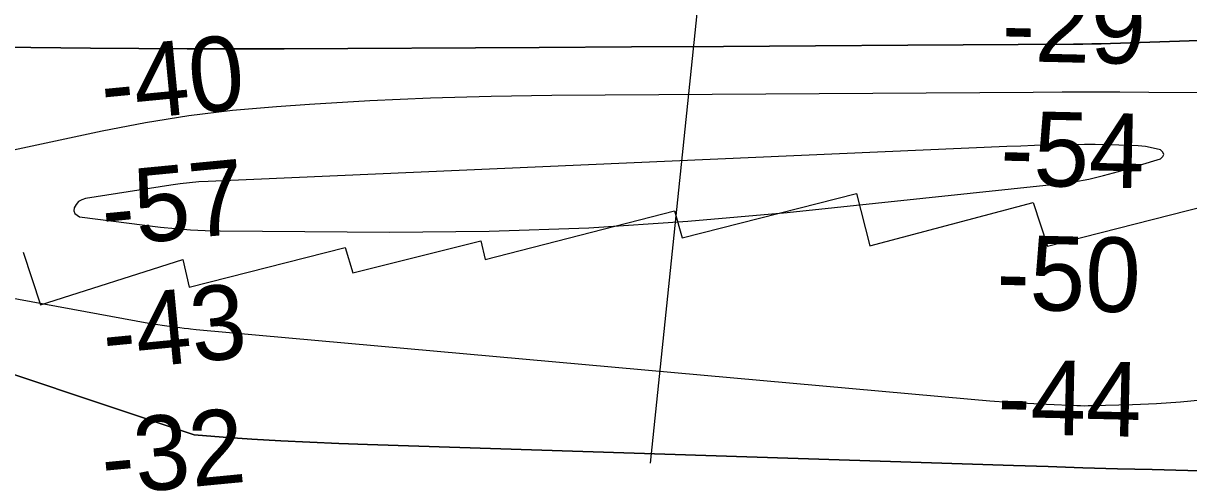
# Model space of a CAD drawing. Extents: x 3219052 to 3256913, y 800770 to 826146.
# Drawn here: x 3231171 to 3232109, y 817201 to 817568 of the extents above; entities that cross this region are included whole.
import ezdxf

# ---------------------------------------------------------------- set-up
doc = ezdxf.new("R2010")
doc.units = 0
for name, color, linetype in [('V-RIVR-RANG', 7, 'Continuous'), ('V-RRAP-RVMT', 7, 'Continuous'), ('V-TOPO-DPTH', 7, 'Continuous'), ('V-TOPO-MAJR', 7, 'Continuous'), ('V-TOPO-MINR', 7, 'Continuous')]:
    doc.layers.add(name, color=color, linetype=linetype)

msp = doc.modelspace()

# ---------------------------------------------------------------- linework, layer by layer
at = {"layer": 'V-RIVR-RANG'}
msp.add_line((3231742.15, 817854.6), (3231675.46, 817214.06), dxfattribs=at)
at = {"layer": 'V-RRAP-RVMT'}
msp.add_lwpolyline([(3231170.56, 817383.87), (3231184.32, 817341.3), (3231298.98, 817377.83), (3231304.2, 817355.77), (3231429.89, 817387.67), (3231435.99, 817367.07), (3231538.94, 817392.87), (3231542.59, 817377.99), (3231694.95, 817417.14), (3231701.22, 817395.43), (3231841.55, 817431.03), (3231852.44, 817388.93), (3231984.07, 817423.79), (3231995.51, 817388.51), (3232123.05, 817421.08)], dxfattribs=at)
at = {"layer": 'V-TOPO-DPTH'}
for points in [[(3232117.58, 817554.21), (3232046.13, 817551.79), (3232038.72, 817551.57), (3232031.31, 817551.39), (3232023.9, 817551.27), (3232016.5, 817551.19), (3231882.92, 817550.33), (3231808.73, 817549.87), (3231734.53, 817549.42), (3231660.33, 817549), (3231586.13, 817548.59), (3231380.67, 817547.49), (3231341.66, 817547.38), (3231302.65, 817547.4), (3231263.64, 817547.61), (3231224.63, 817547.96), (3230816.06, 817552.63), (3230771.39, 817553.09), (3230726.72, 817553.47), (3230682.05, 817553.73), (3230637.37, 817553.93)], [(3230637.37, 817553.93), (3230682.05, 817553.73), (3230726.72, 817553.47), (3230771.39, 817553.09), (3230816.06, 817552.63), (3231224.63, 817547.96), (3231263.64, 817547.61), (3231302.65, 817547.4), (3231341.66, 817547.38), (3231380.67, 817547.49), (3231586.13, 817548.59), (3231660.33, 817549), (3231734.53, 817549.42), (3231808.73, 817549.87), (3231882.92, 817550.33), (3232016.5, 817551.19), (3232023.9, 817551.27), (3232031.31, 817551.39), (3232038.72, 817551.57), (3232046.13, 817551.79), (3232117.58, 817554.21)], [(3230661.51, 817435.89), (3230790.55, 817395.08), (3231011.77, 817335.66), (3231308.28, 817236.8), (3231331.5, 817234.98), (3231354.75, 817233.37), (3231378.02, 817232.02), (3231401.29, 817230.81), (3231424.57, 817229.81), (3231447.86, 817228.95), (3231968.01, 817212.08), (3231995.96, 817211.19), (3232023.9, 817210.34), (3232051.85, 817209.54), (3232079.8, 817208.76), (3232271.55, 817203.6)], [(3232271.55, 817203.6), (3232079.8, 817208.76), (3232051.85, 817209.54), (3232023.9, 817210.34), (3231995.96, 817211.19), (3231968.01, 817212.08), (3231447.86, 817228.95), (3231424.57, 817229.81), (3231401.29, 817230.81), (3231378.02, 817232.02), (3231354.75, 817233.37), (3231331.5, 817234.98), (3231308.28, 817236.8), (3231011.77, 817335.66), (3230790.55, 817395.08), (3230661.51, 817435.89)]]:
    msp.add_lwpolyline(points, dxfattribs=at)
at = {"layer": 'V-TOPO-MAJR'}
for points in [[(3232488.48, 817509.64), (3232077.08, 817512.4), (3232053.79, 817512.51), (3232030.49, 817512.55), (3232007.2, 817512.51), (3231983.9, 817512.4), (3231596.17, 817509.87), (3231547.33, 817509.11), (3231498.51, 817507.76), (3231449.73, 817505.51), (3231400.97, 817502.68), (3231374.36, 817500.89), (3231339.02, 817497.74), (3231303.83, 817493.59), (3231268.85, 817487.93), (3231234.01, 817481.26), (3231008.21, 817432.98)], [(3230989.93, 817378.38), (3231271.7, 817326.7), (3231275.3, 817326.06), (3231278.91, 817325.47), (3231282.53, 817324.93), (3231286.16, 817324.42), (3231290.11, 817323.92), (3231293.42, 817323.5), (3231296.74, 817323.11), (3231300.06, 817322.72), (3231303.55, 817322.32), (3231305.12, 817322.15), (3231309.85, 817321.68), (3231933.87, 817265.41), (3231949.05, 817264.16), (3231964.24, 817263.05), (3231979.44, 817262.16), (3231994.66, 817261.42), (3232019.1, 817260.41), (3232022.1, 817260.31), (3232025.11, 817260.26), (3232028.11, 817260.27), (3232031.11, 817260.31), (3232063.92, 817261.14), (3232083.3, 817261.99), (3232102.64, 817263.31), (3232121.91, 817265.35)]]:
    msp.add_lwpolyline(points, dxfattribs=at)
at = {"layer": 'V-TOPO-MINR'}
for points in [[(3232117.58, 817554.21), (3232046.13, 817551.79), (3232038.72, 817551.57), (3232031.31, 817551.39), (3232023.9, 817551.27), (3232016.5, 817551.19), (3231882.92, 817550.33), (3231808.73, 817549.87), (3231734.53, 817549.42), (3231660.33, 817549), (3231586.13, 817548.59), (3231380.67, 817547.49), (3231341.66, 817547.38), (3231302.65, 817547.4), (3231263.64, 817547.61), (3231224.63, 817547.96), (3230816.06, 817552.63), (3230771.39, 817553.09), (3230726.72, 817553.47), (3230682.05, 817553.73), (3230637.37, 817553.93)], [(3232089.14, 817462.5), (3232088.34, 817464.27), (3232086.48, 817466.04), (3232080.51, 817467.54), (3232074.5, 817468.72), (3232068.4, 817469.42), (3232062.26, 817469.79), (3232033.94, 817470.39), (3232029.59, 817470.44), (3232027.42, 817470.43), (3232025.24, 817470.41), (3232007.34, 817470.11), (3231996.22, 817469.88), (3231985.1, 817469.59), (3231973.98, 817469.21), (3231962.86, 817468.77), (3231319.37, 817440.79), (3231311.86, 817440.34), (3231304.37, 817439.72), (3231296.91, 817438.84), (3231289.46, 817437.8), (3231220.61, 817426.94), (3231217.64, 817425.95), (3231215.06, 817424.46), (3231213.08, 817422.24), (3231211.51, 817419.52), (3231211.37, 817416.98), (3231211.93, 817414.86), (3231215.86, 817412.31), (3231281.18, 817404.04), (3231293.13, 817402.75), (3231305.11, 817401.74), (3231317.11, 817401.16), (3231329.13, 817400.86), (3231465.61, 817399.94), (3231545.82, 817400.75), (3231625.94, 817403.36), (3231705.92, 817408.66), (3231785.82, 817415.75), (3232004.43, 817438.86), (3232016.63, 817440.51), (3232028.74, 817442.61), (3232040.71, 817445.39), (3232052.58, 817448.64), (3232086.51, 817458.95), (3232088.35, 817460.73), (3232089.14, 817462.5)], [(3230661.51, 817435.89), (3230790.55, 817395.08), (3231011.77, 817335.66), (3231308.28, 817236.8), (3231331.5, 817234.98), (3231354.75, 817233.37), (3231378.02, 817232.02), (3231401.29, 817230.81), (3231424.57, 817229.81), (3231447.86, 817228.95), (3231968.01, 817212.08), (3231995.96, 817211.19), (3232023.9, 817210.34), (3232051.85, 817209.54), (3232079.8, 817208.76), (3232271.55, 817203.6)]]:
    msp.add_lwpolyline(points, dxfattribs=at)

# ---------------------------------------------------------------- texts
at = {"layer": 'V-RIVR-RANG'}
for s, rotation, p in [('-29', 358.69158, (3231958.2, 817537.77)), ('-40', 5.50514, (3231235.38, 817488.44)), ('-54', 358.69158, (3231957.02, 817437.77)), ('-57', 5.50514, (3231236, 817388.34)), ('-50', 358.69158, (3231953.95, 817337.82)), ('-43', 5.50514, (3231236.86, 817288.26)), ('-44', 358.69158, (3231954.66, 817237.78)), ('-32', 5.50514, (3231235.83, 817188.01))]:
    msp.add_text(s, height=60, rotation=rotation, dxfattribs=at).set_placement(p)

doc.saveas('drawing.dxf')
